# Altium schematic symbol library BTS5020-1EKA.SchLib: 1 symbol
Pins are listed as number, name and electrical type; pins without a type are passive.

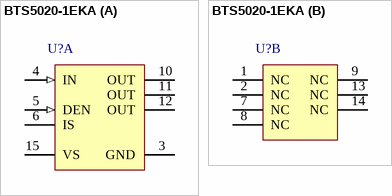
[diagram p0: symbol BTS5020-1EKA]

## BTS5020-1EKA
designator U?
PROFET+ 12 V Smart High-Side Power Switch, 1 Channel, 20 mOhm, 6.5 A Load Current, -40 to 150 degC, PG-DSO-14-47, Reel, Green; Manufacturer: Infineon; PartNumber: BTS5020-1EKA; Channels: 1; Green: TRUE; Group: Automotive Qualified; Load Current (typ): 6.5 A; Ptot (max): 1.8 W; Recommended Operating Voltage Max.: 28 V; Recommended Operating Voltage Min.: 5 V; RON @ 25degreesC: 20 mOhm; RON(max) @ 150degreesC: 44 mOhm; toff (max): 230 us
footprint INF-PG-DSO-14-47_N (SOP, 14-Leads, Body 8.65x3.9mm, Pitch 1.27mm, Thermal Pad 6500x2750mm, IPC Medium Density)
footprint INF-PG-DSO-14-47_L (SOP, 14-Leads, Body 8.65x3.9mm, Pitch 1.27mm, Thermal Pad 6500x2750mm, IPC High Density)
footprint INF-PG-DSO-14-47_M (SOP, 14-Leads, Body 8.65x3.9mm, Pitch 1.27mm, Thermal Pad 6500x2750mm, IPC Low Density)
part A pins: 3 GND (power) "GrouND; Ground connection", 4 IN (in) "INput channel; Input signal for channel activation", 5 DEN (in) "Diagnostic ENable; Digital signal to enable/disable the diagnosis of the device", 6 IS (hiz) "Sense; Sense current of the selected channel", 10 OUT (power) "OUTput; Protected high side power output channel", 11 OUT (power) "OUTput; Protected high side power output channel", 12 OUT (power) "OUTput; Protected high side power output channel", 15 VS (power) "Voltage Supply; Battery voltage"
part B pins: 1 NC "Not Connected; No internal connection to the chip", 2 NC "Not Connected; No internal connection to the chip", 7 NC "Not Connected; No internal connection to the chip", 8 NC "Not Connected; No internal connection to the chip", 9 NC "Not Connected; No internal connection to the chip", 13 NC "Not Connected; No internal connection to the chip", 14 NC "Not Connected; No internal connection to the chip"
